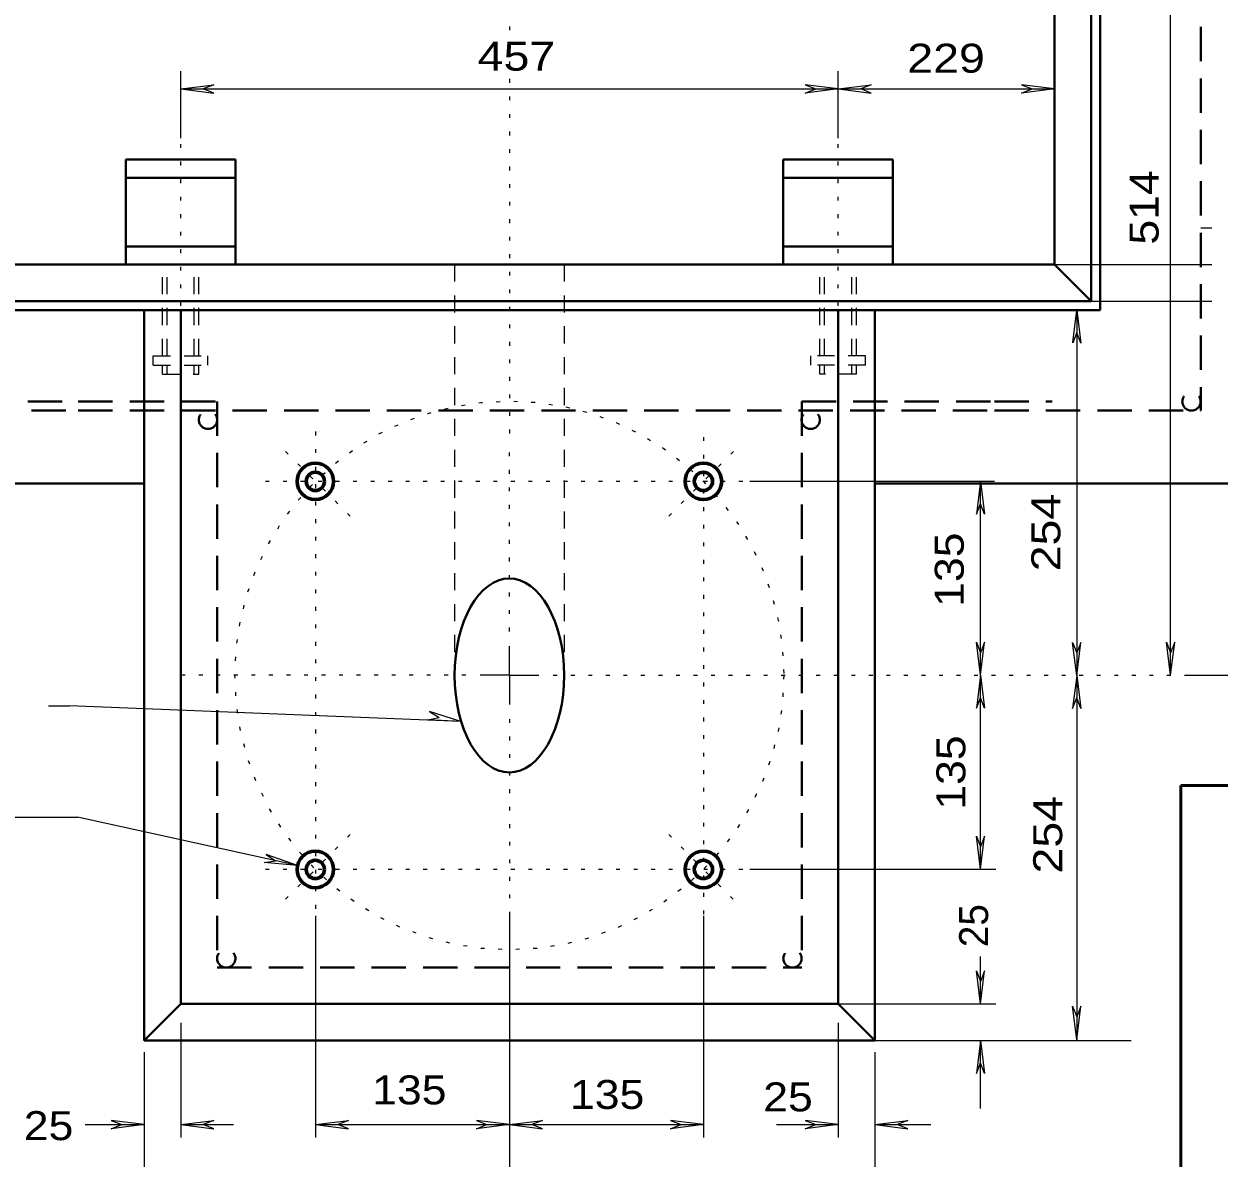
# Model space of a CAD drawing. Extents: x 312583 to 312854, y 144419 to 144597.
# Drawn here: x 312636.57 to 312667.92, y 144513.6 to 144543.37 of the extents above; entities that cross this region are included whole.
import ezdxf

# ---------------------------------------------------------------- set-up
doc = ezdxf.new("R2010")
doc.units = 0
doc.header["$LTSCALE"] = 0.3
for name, pattern in [('DOTTED', [1.5, 0.3, -1.2]), ('MEDIUM_DASHED', [4.5, 3, -1.5]), ('SHORT_DASHED', [2.7, 1.5, -1.2])]:
    doc.linetypes.add(name, pattern=pattern)
doc.layers.add('1', color=7, linetype='Continuous', lineweight=13)

msp = doc.modelspace()

# ---------------------------------------------------------------- linework, layer by layer
at = {"layer": '1', "linetype": 'MEDIUM_DASHED', "lineweight": 40}
for p, q in [((312667.4422, 144558.1369), (312667.4422, 144533.2202)), ((312656.9734, 144533.4579), (312656.9734, 144518.6075)), ((312631.3635, 144533.2202), (312637.9923, 144533.2202))]:
    msp.add_line(p, q, dxfattribs=at)
at = {"layer": '1', "lineweight": 40}
for p, q in [((312664.5672, 144555.2619), (312664.5672, 144536.0952)), ((312664.8049, 144555.4995), (312664.8049, 144535.8575)), ((312663.6089, 144545.6325), (312663.6089, 144537.0535)), ((312639.2404, 144539.8059), (312642.1154, 144539.8059)), ((312639.2404, 144537.0535), (312639.2404, 144539.8059)), ((312642.1154, 144537.0535), (312642.1154, 144539.8059)), ((312659.3654, 144539.8059), (312656.4904, 144539.8059)), ((312656.4904, 144537.0535), (312656.4904, 144539.8059)), ((312659.3654, 144537.0535), (312659.3654, 144539.8059)), ((312639.2404, 144539.3305), (312642.1154, 144539.3305)), ((312659.3654, 144539.3305), (312656.4904, 144539.3305)), ((312639.2404, 144537.5289), (312642.1154, 144537.5289)), ((312659.3654, 144537.5289), (312656.4904, 144537.5289)), ((312635.1968, 144537.0535), (312637.9923, 144537.0535)), ((312663.6089, 144537.0535), (312664.5672, 144536.0952)), ((312634.2385, 144536.0952), (312637.9923, 144536.0952)), ((312633.9931, 144535.8575), (312637.9923, 144535.8575)), ((312640.6817, 144535.8575), (312640.6817, 144517.6492)), ((312657.9317, 144535.8575), (312657.9317, 144517.6492)), ((312658.89, 144535.8575), (312658.89, 144516.6909)), ((312640.6817, 144517.6492), (312639.7234, 144516.6909)), ((312640.6817, 144517.6492), (312657.9317, 144517.6492)), ((312657.9317, 144517.6492), (312658.89, 144516.6909))]:
    msp.add_line(p, q, dxfattribs=at)
at = {"layer": '1'}
for p, q in [((312666.6526, 144526.2742), (312666.6526, 144545.6785)), ((312640.6817, 144540.3655), (312640.6817, 144542.1289)), ((312657.9317, 144540.3655), (312657.9317, 144542.1289)), ((312640.6817, 144541.6612), (312641.548, 144541.7685)), ((312641.548, 144541.7685), (312641.272, 144541.6612)), ((312657.0654, 144541.7685), (312657.3414, 144541.6612)), ((312657.9317, 144541.6612), (312657.0654, 144541.7685)), ((312657.9317, 144541.6612), (312658.798, 144541.7685)), ((312658.798, 144541.7685), (312658.522, 144541.6612)), ((312662.7426, 144541.7685), (312663.0186, 144541.6612)), ((312663.6089, 144541.6612), (312662.7426, 144541.7685)), ((312640.6817, 144541.6612), (312657.9317, 144541.6612)), ((312640.6817, 144541.6612), (312641.548, 144541.5539)), ((312641.548, 144541.5539), (312641.272, 144541.6612)), ((312657.0654, 144541.5539), (312657.3414, 144541.6612)), ((312657.9317, 144541.6612), (312657.0654, 144541.5539)), ((312657.9317, 144541.6612), (312658.798, 144541.5539)), ((312658.798, 144541.5539), (312658.522, 144541.6612)), ((312662.7426, 144541.5539), (312663.0186, 144541.6612)), ((312663.6089, 144541.6612), (312662.7426, 144541.5539)), ((312655.6087, 144531.3649), (312662.0319, 144531.3649)), ((312661.6654, 144531.3649), (312661.558, 144530.4985)), ((312661.6654, 144531.3649), (312661.7727, 144530.4985)), ((312661.558, 144530.4985), (312661.6654, 144530.7745)), ((312661.7727, 144530.4985), (312661.6654, 144530.7745)), ((312649.3067, 144526.2742), (312649.3067, 144527.0409)), ((312661.558, 144527.1405), (312661.6654, 144526.8645)), ((312661.6654, 144526.2742), (312661.558, 144527.1405)), ((312661.7727, 144527.1405), (312661.6654, 144526.8645)), ((312661.6654, 144526.2742), (312661.7727, 144527.1405)), ((312664.0817, 144527.1383), (312664.189, 144526.8623)), ((312664.189, 144526.272), (312664.0817, 144527.1383)), ((312664.2963, 144527.1383), (312664.189, 144526.8623)), ((312664.189, 144526.272), (312664.2963, 144527.1383)), ((312666.5452, 144527.1405), (312666.6526, 144526.8645)), ((312666.6526, 144526.2742), (312666.5452, 144527.1405)), ((312666.7599, 144527.1405), (312666.6526, 144526.8645)), ((312666.6526, 144526.2742), (312666.7599, 144527.1405)), ((312649.3067, 144526.2742), (312648.54, 144526.2742)), ((312649.3067, 144526.2742), (312649.3067, 144525.5075)), ((312649.3067, 144526.2742), (312650.0734, 144526.2742)), ((312661.6654, 144526.2742), (312661.558, 144525.4079)), ((312661.6654, 144526.2742), (312661.7727, 144525.4079)), ((312664.189, 144526.272), (312664.0817, 144525.4057)), ((312664.189, 144526.272), (312664.2963, 144525.4057)), ((312667.0627, 144526.2742), (312670.2597, 144526.2742)), ((312637.2108, 144525.4687), (312637.7613, 144525.4687)), ((312648.034, 144525.0629), (312637.7613, 144525.4687)), ((312661.558, 144525.4079), (312661.6654, 144525.6839)), ((312661.7727, 144525.4079), (312661.6654, 144525.6839)), ((312664.0817, 144525.4057), (312664.189, 144525.6817)), ((312664.2963, 144525.4057), (312664.189, 144525.6817)), ((312647.1677, 144525.1089), (312647.459, 144525.1702)), ((312648.034, 144525.0629), (312647.1677, 144525.1089)), ((312647.206, 144525.3235), (312647.459, 144525.1702)), ((312648.034, 144525.0629), (312647.206, 144525.3235)), ((312636.212, 144522.5482), (312637.9754, 144522.5482)), ((312643.7407, 144521.2832), (312637.9754, 144522.5482)), ((312661.558, 144522.0499), (312661.6654, 144521.7739)), ((312661.6654, 144521.1835), (312661.558, 144522.0499)), ((312661.7727, 144522.0499), (312661.6654, 144521.7739)), ((312661.6654, 144521.1835), (312661.7727, 144522.0499)), ((312642.8744, 144521.3599), (312643.1657, 144521.4059)), ((312643.7407, 144521.2832), (312642.8744, 144521.3599)), ((312642.9204, 144521.5745), (312643.1657, 144521.4059)), ((312643.7407, 144521.2832), (312642.9204, 144521.5745)), ((312655.6087, 144521.1835), (312662.064, 144521.1835)), ((312644.216, 144519.9645), (312644.216, 144514.1455)), ((312649.3067, 144519.9645), (312649.3067, 144511.4545)), ((312654.3974, 144519.9645), (312654.3974, 144514.1455)), ((312661.6654, 144517.6492), (312661.6654, 144518.8928)), ((312661.558, 144518.5155), (312661.6654, 144518.2395)), ((312661.6654, 144517.6492), (312661.558, 144518.5155)), ((312661.7727, 144518.5155), (312661.6654, 144518.2395)), ((312661.6654, 144517.6492), (312661.7727, 144518.5155)), ((312657.9317, 144517.6492), (312662.064, 144517.6492)), ((312664.0818, 144517.5868), (312664.1891, 144517.3108)), ((312664.1891, 144516.7205), (312664.0818, 144517.5868)), ((312664.2964, 144517.5868), (312664.1891, 144517.3108)), ((312664.1891, 144516.7205), (312664.2964, 144517.5868)), ((312640.6817, 144517.1509), (312640.6817, 144514.1455)), ((312657.9317, 144517.1509), (312657.9317, 144514.1455)), ((312658.89, 144516.6909), (312665.6137, 144516.6909)), ((312661.6654, 144516.6909), (312661.558, 144515.8245)), ((312661.6654, 144514.9045), (312661.6654, 144516.6909)), ((312661.6654, 144516.6909), (312661.7727, 144515.8245)), ((312639.7234, 144516.3842), (312639.7234, 144508.9092)), ((312658.89, 144516.3842), (312658.89, 144508.9092)), ((312661.558, 144515.8245), (312661.6654, 144516.1005)), ((312661.7727, 144515.8245), (312661.6654, 144516.1005)), ((312638.1747, 144514.4829), (312639.7234, 144514.4829)), ((312638.857, 144514.5902), (312639.133, 144514.4829)), ((312639.7234, 144514.4829), (312638.857, 144514.5902)), ((312638.857, 144514.3755), (312639.133, 144514.4829)), ((312639.7234, 144514.4829), (312638.857, 144514.3755)), ((312640.6817, 144514.4829), (312641.548, 144514.5902)), ((312640.6817, 144514.4829), (312642.0617, 144514.4829)), ((312640.6817, 144514.4829), (312641.548, 144514.3755)), ((312641.548, 144514.5902), (312641.272, 144514.4829)), ((312641.548, 144514.3755), (312641.272, 144514.4829)), ((312644.216, 144514.4829), (312645.0824, 144514.5902)), ((312644.216, 144514.4829), (312649.3067, 144514.4829)), ((312644.216, 144514.4829), (312645.0824, 144514.3755)), ((312645.0824, 144514.5902), (312644.8064, 144514.4829)), ((312645.0824, 144514.3755), (312644.8064, 144514.4829)), ((312648.4404, 144514.5902), (312648.7164, 144514.4829)), ((312649.3067, 144514.4829), (312648.4404, 144514.5902)), ((312648.4404, 144514.3755), (312648.7164, 144514.4829)), ((312649.3067, 144514.4829), (312648.4404, 144514.3755)), ((312649.3067, 144514.4829), (312650.173, 144514.5902)), ((312649.3067, 144514.4829), (312654.3974, 144514.4829)), ((312649.3067, 144514.4829), (312650.173, 144514.3755)), ((312650.173, 144514.5902), (312649.897, 144514.4829)), ((312650.173, 144514.3755), (312649.897, 144514.4829)), ((312653.531, 144514.5902), (312653.807, 144514.4829)), ((312654.3974, 144514.4829), (312653.531, 144514.5902)), ((312653.531, 144514.3755), (312653.807, 144514.4829)), ((312654.3974, 144514.4829), (312653.531, 144514.3755)), ((312656.314, 144514.4829), (312657.9317, 144514.4829)), ((312657.0654, 144514.5902), (312657.3414, 144514.4829)), ((312657.9317, 144514.4829), (312657.0654, 144514.5902)), ((312657.0654, 144514.3755), (312657.3414, 144514.4829)), ((312657.9317, 144514.4829), (312657.0654, 144514.3755)), ((312658.89, 144514.4829), (312659.7564, 144514.5902)), ((312658.89, 144514.4829), (312660.362, 144514.4829)), ((312658.89, 144514.4829), (312659.7564, 144514.3755)), ((312659.7564, 144514.5902), (312659.4804, 144514.4829)), ((312659.7564, 144514.3755), (312659.4804, 144514.4829))]:
    msp.add_line(p, q, dxfattribs=at)
at = {"layer": '1', "linetype": 'DOTTED'}
for p, q in [((312649.3067, 144545.1419), (312649.3067, 144532.3232)), ((312640.6817, 144533.6725), (312640.6817, 144540.3655)), ((312657.9317, 144533.6725), (312657.9317, 144540.3655)), ((312644.216, 144532.6682), (312644.216, 144519.9645)), ((312645.1284, 144530.4525), (312643.2424, 144532.3309)), ((312649.3067, 144527.4242), (312649.3067, 144532.3232)), ((312653.485, 144530.4525), (312655.3634, 144532.3309)), ((312654.3974, 144532.5225), (312654.3974, 144519.9645)), ((312642.905, 144531.3649), (312655.6087, 144531.3649)), ((312648.1567, 144526.2742), (312640.49, 144526.2742)), ((312650.4567, 144526.2742), (312667.0627, 144526.2742)), ((312649.3067, 144525.1242), (312649.3067, 144519.9645)), ((312645.1284, 144522.0959), (312643.2424, 144520.2099)), ((312653.485, 144522.0959), (312655.3634, 144520.2099)), ((312642.905, 144521.1835), (312655.6087, 144521.1835))]:
    msp.add_line(p, q, dxfattribs=at)
at = {"layer": '1', "lineweight": 25}
for p, q in [((312667.4422, 144538.0119), (312667.7336, 144538.0119)), ((312663.6089, 144537.0535), (312667.7336, 144537.0535)), ((312664.5672, 144536.0952), (312667.7336, 144536.0952))]:
    msp.add_line(p, q, dxfattribs=at)
at = {"layer": '1', "linetype": 'SHORT_DASHED', "lineweight": 25}
for p, q in [((312640.1987, 144534.6539), (312640.1987, 144537.0535)), ((312640.3214, 144534.6539), (312640.3214, 144537.0535)), ((312641.0344, 144534.6539), (312641.0344, 144537.0535)), ((312641.157, 144534.6539), (312641.157, 144537.0535)), ((312647.8654, 144537.0535), (312647.8654, 144526.2742)), ((312650.7404, 144537.0535), (312650.7404, 144526.2742)), ((312657.4487, 144534.6539), (312657.4487, 144537.0535)), ((312657.5714, 144534.6539), (312657.5714, 144537.0535)), ((312658.2844, 144534.6539), (312658.2844, 144537.0535)), ((312658.407, 144534.6539), (312658.407, 144537.0535)), ((312639.961, 144534.6539), (312641.3947, 144534.6539)), ((312639.961, 144534.4162), (312639.961, 144534.6539)), ((312641.3947, 144534.4162), (312641.3947, 144534.6539)), ((312658.6447, 144534.6539), (312657.211, 144534.6539)), ((312657.211, 144534.4162), (312657.211, 144534.6539)), ((312658.6447, 144534.4162), (312658.6447, 144534.6539)), ((312639.961, 144534.4162), (312641.3947, 144534.4162)), ((312640.1987, 144534.1785), (312640.1987, 144534.4162)), ((312640.3214, 144534.1785), (312640.3214, 144534.4162)), ((312641.0344, 144534.1785), (312641.0344, 144534.4162)), ((312641.157, 144534.1785), (312641.157, 144534.4162)), ((312658.6447, 144534.4162), (312657.211, 144534.4162)), ((312657.4487, 144534.1785), (312657.4487, 144534.4162)), ((312657.5714, 144534.1785), (312657.5714, 144534.4162)), ((312658.2844, 144534.1785), (312658.2844, 144534.4162)), ((312658.407, 144534.1785), (312658.407, 144534.4162)), ((312640.1987, 144534.1785), (312641.157, 144534.1785)), ((312658.407, 144534.1785), (312657.4487, 144534.1785))]:
    msp.add_line(p, q, dxfattribs=at)
at = {"layer": '1', "lineweight": 53}
for p in [(312689.9495, 144523.38), (312666.9226, 144486.1644)]:
    msp.add_line(p, (312666.9226, 144523.38), dxfattribs=at)
at = {"layer": '1'}
for points in [[(312657.9317, 144541.6612), (312662.0319, 144541.6612), (312663.6089, 144541.6612)], [(312664.1875, 144535.8575), (312664.1875, 144526.0176), (312664.1875, 144516.6909)], [(312661.6654, 144521.1835), (312661.6654, 144526.2742), (312661.6654, 144531.3649)]]:
    msp.add_lwpolyline(points, dxfattribs=at)
at = {"layer": '1', "lineweight": 40}
for points in [[(312637.9923, 144537.0535), (312662.0319, 144537.0535), (312663.6089, 144537.0535)], [(312637.9923, 144536.0952), (312662.0319, 144536.0952), (312664.5672, 144536.0952)], [(312637.9923, 144535.8575), (312662.0319, 144535.8575), (312664.8049, 144535.8575)], [(312639.7234, 144535.8575), (312639.7234, 144516.6909), (312658.89, 144516.6909)], [(312629.4468, 144531.3035), (312637.9923, 144531.3035), (312639.7234, 144531.3035)], [(312658.89, 144531.3035), (312662.0319, 144531.3035), (312669.3589, 144531.3035)]]:
    msp.add_lwpolyline(points, dxfattribs=at)
at = {"layer": '1'}
msp.add_lwpolyline([(312664.0825, 144535.0098), (312664.1875, 144535.8575), (312664.2948, 144534.9912), (312664.1875, 144535.2672), (312664.0825, 144534.9971)], close=True, dxfattribs=at)
at = {"layer": '1', "linetype": 'MEDIUM_DASHED', "lineweight": 40}
for points in [[(312635.3195, 144533.4579), (312637.9923, 144533.4579), (312641.64, 144533.4579)], [(312641.64, 144533.4579), (312641.64, 144518.6075), (312656.9734, 144518.6075)], [(312656.9734, 144533.4579), (312662.0319, 144533.4579), (312663.5476, 144533.4579)], [(312637.9923, 144533.2202), (312662.0319, 144533.2202), (312667.4422, 144533.2202)]]:
    msp.add_lwpolyline(points, dxfattribs=at)
for centre in [(312667.1988, 144533.4579), (312641.3966, 144532.9787), (312657.2091, 144532.9787), (312641.8758, 144518.8433), (312656.73, 144518.8433)]:
    msp.add_circle(centre, 0.2396, dxfattribs=at)
at = {"layer": '1', "linetype": 'DOTTED'}
msp.add_circle((312649.3029, 144526.2704), 7.2007, dxfattribs=at)
at = {"layer": '1', "lineweight": 60}
for centre, radius in [((312644.2112, 144531.362), 0.4792), ((312654.3945, 144531.362), 0.4792), ((312644.2112, 144531.362), 0.2396), ((312654.3945, 144531.362), 0.2396), ((312644.2112, 144521.1787), 0.4792), ((312654.3945, 144521.1787), 0.4792), ((312644.2112, 144521.1787), 0.2396), ((312654.3945, 144521.1787), 0.2396)]:
    msp.add_circle(centre, radius, dxfattribs=at)
at = {"layer": '1', "lineweight": 40}
msp.add_ellipse((312649.3029, 144526.2708), major_axis=(0, -2.5458), ratio=0.564653, dxfattribs=at)

# ---------------------------------------------------------------- texts
at = {"layer": '1'}
for s, width, p in [('457 ', 1.2, (312648.4711, 144542.1406)), ('229 ', 1.2, (312659.7438, 144542.088)), ('135 ', 1.15, (312645.7045, 144515.0137)), ('135 ', 1.15, (312650.8938, 144514.8941)), ('25 ', 1.15, (312655.9637, 144514.8304)), ('25 ', 1.15, (312636.5637, 144514.0756))]:
    msp.add_text(s, height=0.76, dxfattribs=dict(at, width=width)).set_placement(p)
for s, width, p in [('514 ', 1.15, (312666.3359, 144537.5751)), ('254 ', 1.2, (312663.7587, 144529.0026)), ('135 ', 1.15, (312661.2249, 144528.0704)), ('135 ', 1.15, (312661.2669, 144522.7469)), ('254 ', 1.2, (312663.8072, 144521.0716))]:
    msp.add_text(s, height=0.76, rotation=90, dxfattribs=dict(at, width=width)).set_placement(p)
msp.add_text('25', height=0.76, rotation=90, dxfattribs=at).set_placement((312661.864, 144519.1383))

doc.saveas('drawing.dxf')
